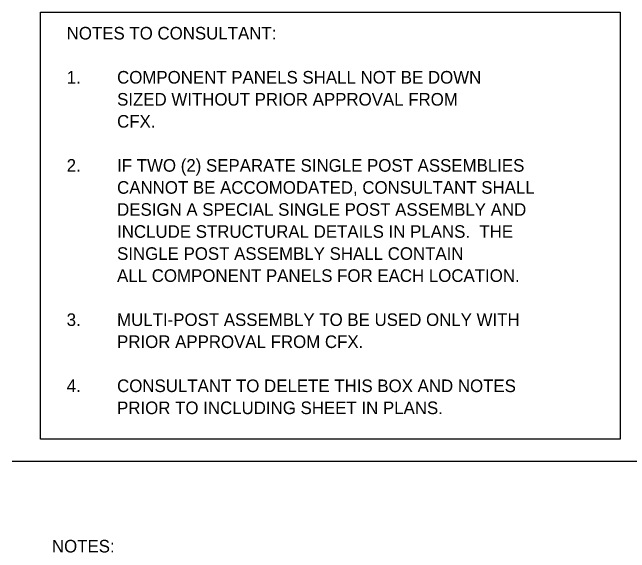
# Model space of a CAD drawing. Extents: x 530729 to 531367, y 1533250 to 1533664.
# Drawn here: x 530751.5 to 530888.6, y 1533457.4 to 1533577.5 of the extents above; entities that cross this region are included whole.
import ezdxf

# ---------------------------------------------------------------- set-up
doc = ezdxf.new("R2010")
doc.units = 0
for name, color, linetype in [('SheetBorder_dp', 7, 'Continuous'), ('TextAlert', 7, 'Continuous'), ('TextLabel', 7, 'Continuous')]:
    doc.layers.add(name, color=color, linetype=linetype)

msp = doc.modelspace()

# ---------------------------------------------------------------- linework, layer by layer
at = {"layer": 'SheetBorder_dp'}
msp.add_line((530751.46, 1533477.75), (531367.46, 1533477.75), dxfattribs=at)
at = {"layer": 'TextAlert'}
msp.add_lwpolyline([(530757.73, 1533577.53), (530886.52, 1533577.53), (530886.52, 1533482.62), (530757.73, 1533482.62)], close=True, dxfattribs=at)

# ---------------------------------------------------------------- texts
for s, p in [('NOTES TO CONSULTANT:', (530763.54, 1533571.49)), ('1.', (530763.54, 1533561.69)), ('COMPONENT PANELS SHALL NOT BE DOWN', (530774.74, 1533561.69)), ('SIZED WITHOUT PRIOR APPROVAL FROM', (530774.74, 1533556.79)), ('CFX.', (530774.74, 1533551.89)), ('2.', (530763.54, 1533542.09)), ('IF TWO (2) SEPARATE SINGLE POST ASSEMBLIES', (530774.74, 1533542.09)), ('CANNOT BE ACCOMODATED, CONSULTANT SHALL', (530774.74, 1533537.19)), ('DESIGN A SPECIAL SINGLE POST ASSEMBLY AND', (530774.74, 1533532.29)), ('INCLUDE STRUCTURAL DETAILS IN PLANS.  THE', (530774.74, 1533527.39)), ('SINGLE POST ASSEMBLY SHALL CONTAIN', (530774.74, 1533522.49)), ('ALL COMPONENT PANELS FOR EACH LOCATION. ', (530774.74, 1533517.59)), ('3.', (530763.54, 1533507.79)), ('MULTI-POST ASSEMBLY TO BE USED ONLY WITH', (530774.74, 1533507.79)), ('PRIOR APPROVAL FROM CFX.', (530774.74, 1533502.89)), ('4.', (530763.54, 1533493.09)), ('CONSULTANT TO DELETE THIS BOX AND NOTES', (530774.74, 1533493.09)), ('PRIOR TO INCLUDING SHEET IN PLANS.', (530774.74, 1533488.19))]:
    msp.add_text(s, height=2.8, dxfattribs=at).set_placement(p)
at = {"layer": 'TextLabel'}
msp.add_text('NOTES:', height=2.8, dxfattribs=at).set_placement((530760.26, 1533457.43))

doc.saveas('drawing.dxf')
